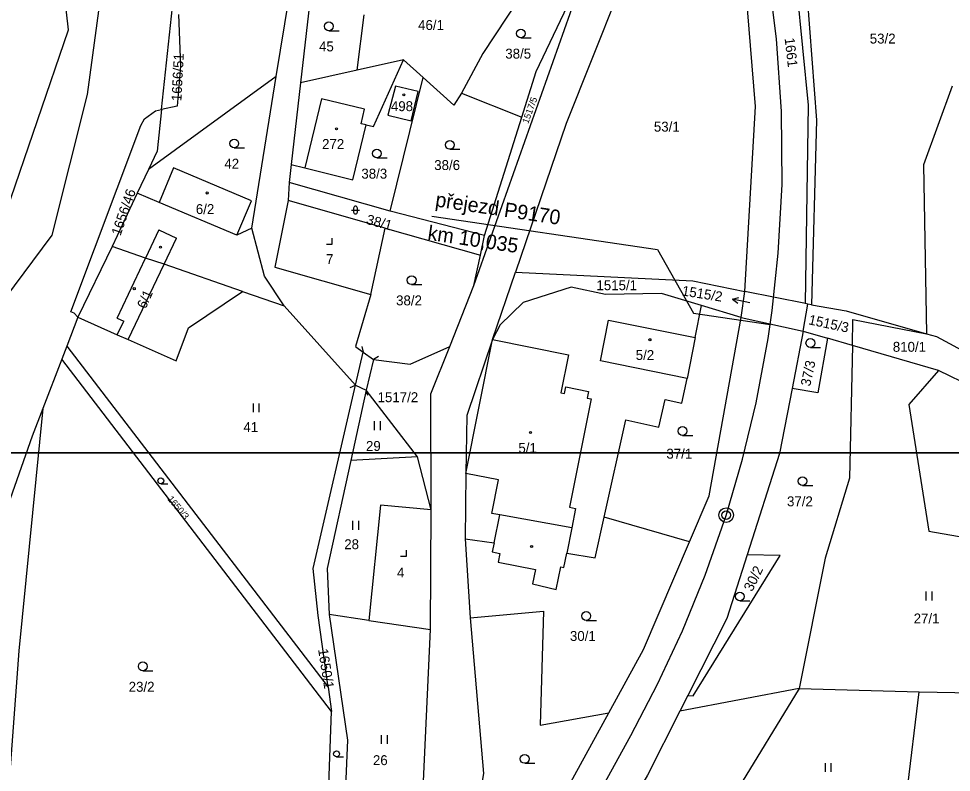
# Model space of a CAD drawing. Extents: x -553916 to -552953, y -1067470 to -1066637.
# Drawn here: x -553633.4 to -553473.7, y -1067154.7 to -1067025.6 of the extents above; entities that cross this region are included whole.
import ezdxf

# ---------------------------------------------------------------- set-up
doc = ezdxf.new("R2010")
doc.units = 0
for name, color, linetype in [('Hranice parcel', 7, 'Continuous'), ('Kolej', 7, 'Continuous'), ('Návěst místo trati', 7, 'Continuous'), ('Parcelní čísla', 7, 'Continuous'), ('Pop  PČ popisy', 7, 'Continuous'), ('Propustek', 7, 'Continuous'), ('Přejezd - štěrkové lože', 7, 'Continuous'), ('Vnitřní kresba', 7, 'Continuous'), ('Vrstva 1', 7, 'Continuous'), ('Značky budov', 7, 'Continuous'), ('Značky kultur', 7, 'Continuous')]:
    doc.layers.add(name, color=color, linetype=linetype)

msp = doc.modelspace()

# ---------------------------------------------------------------- linework, layer by layer
at = {"layer": 'Hranice parcel'}
for p, q in [((-553589.31, -1067035.5), (-553580.85, -1066983.77)), ((-553608.97, -1067041.18), (-553606.12, -1067014.56)), ((-553555.44, -1067071.33), (-553535.85, -1067015.85)), ((-553575.44, -1067034.44), (-553574.24, -1067024.96)), ((-553567.53, -1067032.65), (-553575.44, -1067034.44)), ((-553564.16, -1067035.68), (-553567.53, -1067032.65)), ((-553575.44, -1067034.44), (-553585.14, -1067036.63)), ((-553589.31, -1067035.5), (-553611.2, -1067051.45)), ((-553593.47, -1067061.49), (-553589.31, -1067035.5)), ((-553585.14, -1067036.63), (-553586.75, -1067050.6)), ((-553569.79, -1067058.6), (-553564.16, -1067035.68)), ((-553557.59, -1067038.38), (-553547.23, -1067042.51)), ((-553473.53, -1067037.17), (-553478.45, -1067050.68)), ((-553473.53, -1067037.17), (-553478.45, -1067050.68)), ((-553610, -1067041.4), (-553608.97, -1067041.18)), ((-553606.25, -1067040.6), (-553608.97, -1067041.18)), ((-553553.65, -1067062.79), (-553547.23, -1067042.51)), ((-553586.75, -1067050.6), (-553587.12, -1067053.68)), ((-553586.75, -1067050.6), (-553584.42, -1067051.17)), ((-553478.45, -1067050.68), (-553477.96, -1067079.63)), ((-553478.45, -1067050.68), (-553477.96, -1067079.63)), ((-553611.2, -1067051.45), (-553613.12, -1067055.53)), ((-553587.12, -1067053.68), (-553587.28, -1067056.75)), ((-553569.79, -1067058.6), (-553587.12, -1067053.68)), ((-553613.12, -1067055.53), (-553617.4, -1067064.65)), ((-553609.37, -1067057.11), (-553613.12, -1067055.53)), ((-553570.64, -1067061.48), (-553587.28, -1067056.75)), ((-553553.65, -1067062.79), (-553569.79, -1067058.6)), ((-553593.47, -1067061.49), (-553596.05, -1067062.7)), ((-553573.09, -1067072.86), (-553570.64, -1067061.48)), ((-553570.64, -1067061.48), (-553554.35, -1067066.11)), ((-553554.35, -1067066.11), (-553553.65, -1067062.79)), ((-553617.4, -1067064.65), (-553623.27, -1067076.77)), ((-553555.44, -1067071.33), (-553554.35, -1067066.11)), ((-553552.27, -1067080.57), (-553548.33, -1067069.03)), ((-553559.6, -1067081.76), (-553555.44, -1067071.33)), ((-553595.06, -1067072.35), (-553587.94, -1067074.8)), ((-553575.72, -1067088.37), (-553587.94, -1067074.8)), ((-553517.54, -1067080.21), (-553516.45, -1067074.75)), ((-553509.66, -1067076.78), (-553516.45, -1067074.75)), ((-553623.27, -1067076.77), (-553625.16, -1067081.69)), ((-553490.63, -1067081.59), (-553490.53, -1067077.13)), ((-553490.63, -1067081.59), (-553490.53, -1067077.13)), ((-553490.53, -1067077.13), (-553477.96, -1067079.63)), ((-553490.53, -1067077.13), (-553477.96, -1067079.63)), ((-553517.54, -1067080.21), (-553518.94, -1067087.24)), ((-553490.63, -1067081.59), (-553494.87, -1067080.36)), ((-553475.9, -1067085.87), (-553490.63, -1067081.59)), ((-553625.16, -1067081.69), (-553626.04, -1067083.95)), ((-553625.16, -1067081.69), (-553580.41, -1067140.15)), ((-553575.72, -1067088.37), (-553574.42, -1067082.75)), ((-553574.42, -1067082.75), (-553572.66, -1067084.02)), ((-553626.04, -1067083.95), (-553629.28, -1067092.37)), ((-553579.82, -1067144.32), (-553626.04, -1067083.95)), ((-553572.66, -1067084.02), (-553573.91, -1067089.23)), ((-553461.02, -1067093.19), (-553475.9, -1067085.87)), ((-553573.91, -1067089.23), (-553576.54, -1067101.32)), ((-553565.13, -1067100.69), (-553573.91, -1067089.23)), ((-553565.13, -1067100.69), (-553576.54, -1067101.32)), ((-553562.76, -1067109.76), (-553565.13, -1067100.69)), ((-553562.87, -1067130.27), (-553562.76, -1067109.76)), ((-553518.53, -1067115.26), (-553533.13, -1067110.99)), ((-553556.94, -1067114.69), (-553556.09, -1067128.27)), ((-553573.45, -1067128.7), (-553580.27, -1067127.69)), ((-553573.45, -1067128.7), (-553562.87, -1067130.27)), ((-553580.41, -1067140.15), (-553579.82, -1067144.32)), ((-553499.73, -1067140.34), (-553520.16, -1067144.23)), ((-553499.73, -1067140.34), (-553516.39, -1067167.53)), ((-553499.73, -1067140.34), (-553516.39, -1067167.53)), ((-553499.73, -1067140.34), (-553479.18, -1067140.92)), ((-553482.63, -1067169.28), (-553479.18, -1067140.92)), ((-553479.18, -1067140.92), (-553459.64, -1067141.29)), ((-553581.09, -1067176.52), (-553579.82, -1067144.32))]:
    msp.add_line(p, q, dxfattribs=at)
for points in [[(-553623.32, -1066984.67), (-553619.63, -1066996.83), (-553619.56, -1067023.02), (-553621.7, -1067038.64), (-553627.75, -1067062.69), (-553642.34, -1067082.27), (-553644.52, -1067088.87), (-553655.73, -1067178.24), (-553657.73, -1067185.13), (-553660.17, -1067189.87)], [(-553515.43, -1066991.08), (-553526.38, -1067010.19), (-553539.65, -1067043.59), (-553548.33, -1067069.03)], [(-553547.23, -1067042.51), (-553544.77, -1067034.69), (-553535.85, -1067015.85)], [(-553635.52, -1067058.6), (-553624.9, -1067027.54), (-553625.87, -1067018.94)], [(-553547.68, -1067022.12), (-553553.91, -1067031.58), (-553557.59, -1067038.38)], [(-553582.25, -1067023.44), (-553583.62, -1067023.18), (-553585.14, -1067036.63)], [(-553606.05, -1067024.93), (-553605.71, -1067033.75), (-553606.25, -1067040.6)], [(-553573.91, -1067043.82), (-553572.67, -1067044.12), (-553567.53, -1067032.65)], [(-553557.59, -1067038.38), (-553558.91, -1067040.42), (-553564.16, -1067035.68)], [(-553568.89, -1067037.19), (-553570.19, -1067042.13), (-553566.22, -1067043.1), (-553564.98, -1067038.12), (-553568.89, -1067037.19)], [(-553624.48, -1067075.84), (-553612.48, -1067043.92), (-553611.9, -1067042.79), (-553610, -1067041.4)], [(-553608.97, -1067041.18), (-553609.73, -1067048.33), (-553611.2, -1067051.45)], [(-553584.42, -1067051.17), (-553576.18, -1067053.25), (-553573.91, -1067043.82)], [(-553596.05, -1067062.7), (-553593.57, -1067056.8), (-553606.92, -1067051.2), (-553609.37, -1067057.11)], [(-553587.28, -1067056.75), (-553589.54, -1067068.19), (-553573.09, -1067072.86)], [(-553587.94, -1067074.8), (-553591.32, -1067069.72), (-553593.47, -1067061.49)], [(-553595.06, -1067072.35), (-553608.53, -1067067.7), (-553611.68, -1067066.62), (-553617.4, -1067064.65)], [(-553548.33, -1067069.03), (-553517.95, -1067070.55), (-553509.03, -1067072.35)], [(-553516.45, -1067074.75), (-553523.31, -1067072.7), (-553532.92, -1067072.84), (-553538.78, -1067071.62), (-553547.04, -1067074.23), (-553550.96, -1067078.08), (-553552.27, -1067080.57)], [(-553623.27, -1067076.77), (-553616.54, -1067079.76), (-553614.66, -1067080.6), (-553606.47, -1067084.24), (-553604.34, -1067078.59), (-553595.06, -1067072.35)], [(-553573.09, -1067072.86), (-553575.74, -1067081.8), (-553574.42, -1067082.75)], [(-553497.61, -1067074.62), (-553491.7, -1067075.64), (-553477.96, -1067079.63)], [(-553623.27, -1067076.77), (-553623.9, -1067076.05), (-553624.48, -1067075.84)], [(-553518.94, -1067087.24), (-553533.8, -1067084.25), (-553532.39, -1067077.24), (-553517.54, -1067080.21)], [(-553477.96, -1067079.63), (-553476.25, -1067080.06), (-553464.58, -1067086.32)], [(-553552.27, -1067080.57), (-553556.64, -1067093.58), (-553556.86, -1067103.5), (-553556.94, -1067114.69)], [(-553490.63, -1067081.59), (-553491.15, -1067104.31), (-553495.3, -1067118.01), (-553499.73, -1067140.34)], [(-553490.63, -1067081.59), (-553491.15, -1067104.31), (-553495.3, -1067118.01), (-553499.73, -1067140.34)], [(-553572.66, -1067084.02), (-553566.4, -1067084.81), (-553559.6, -1067081.76)], [(-553562.76, -1067109.76), (-553562.85, -1067089.89), (-553559.6, -1067081.76)], [(-553475.9, -1067085.87), (-553480.97, -1067091.73), (-553477.55, -1067113.39), (-553465.08, -1067115.55)], [(-553533.13, -1067110.99), (-553529.45, -1067094.35), (-553523.77, -1067095.61), (-553522.71, -1067090.83), (-553519.87, -1067091.46), (-553518.94, -1067087.24)], [(-553580.41, -1067140.15), (-553582.14, -1067127.86), (-553583, -1067119.78), (-553575.72, -1067088.37)], [(-553629.28, -1067092.37), (-553631.12, -1067097.14), (-553637.98, -1067116.48)], [(-553629.28, -1067092.37), (-553633.37, -1067133.92), (-553635.66, -1067164.7)], [(-553576.54, -1067101.32), (-553580.57, -1067119.79), (-553580.27, -1067127.69)], [(-553562.76, -1067109.76), (-553571.44, -1067108.95), (-553573.45, -1067128.7)], [(-553540.05, -1067119.63), (-553539.55, -1067117.17), (-553534.67, -1067117.97), (-553533.13, -1067110.99)], [(-553556.94, -1067114.69), (-553551.99, -1067115.38), (-553552.31, -1067116.95)], [(-553552.31, -1067116.95), (-553550.99, -1067117.22), (-553551.28, -1067118.69), (-553544.93, -1067119.96), (-553545.42, -1067122.41), (-553541.36, -1067123.37), (-553540.59, -1067119.53), (-553540.05, -1067119.63)], [(-553518.82, -1067141.56), (-553517.91, -1067141.59), (-553503, -1067117.58), (-553508.67, -1067117.46)], [(-553580.27, -1067127.69), (-553577.12, -1067149.23), (-553578.28, -1067177), (-553579.68, -1067182.05)], [(-553556.09, -1067128.27), (-553543.56, -1067127.12), (-553544.12, -1067146.66), (-553532.35, -1067144.53)], [(-553556.09, -1067128.27), (-553553.82, -1067154.93), (-553557.64, -1067176.88)], [(-553569.54, -1067184.03), (-553564.06, -1067156.23), (-553562.87, -1067130.27)]]:
    msp.add_lwpolyline(points, dxfattribs=at)
at = {"layer": 'Kolej'}
for points in [[(-553503.32, -1067065.81), (-553502.68, -1067054.03), (-553502.76, -1067041.5), (-553503.63, -1067029.06), (-553504.76, -1067019.97), (-553506.18, -1067011.39), (-553508.33, -1067001.39), (-553510.95, -1066991.62), (-553512.92, -1066985.29), (-553515.65, -1066977.35), (-553517.42, -1066972.53), (-553519.16, -1066967.95), (-553522.89, -1066958.38), (-553529.1, -1066942.55), (-553538.69, -1066918.11), (-553542.91, -1066907.33), (-553546.69, -1066897.68), (-553555.03, -1066876.44), (-553564.64, -1066851.89), (-553574.24, -1066827.43), (-553583.19, -1066804.62)], [(-553543.17, -1067173.82), (-553538.26, -1067165.53), (-553533.28, -1067156.93), (-553528.57, -1067148.43), (-553524.02, -1067139.63), (-553519.75, -1067130.49), (-553515.84, -1067120.93), (-553512.27, -1067110.73), (-553509.46, -1067101.06), (-553507.13, -1067091.41), (-553505.08, -1067080.38), (-553504.39, -1067075.58), (-553503.32, -1067065.81)]]:
    msp.add_lwpolyline(points, dxfattribs=at)
at = {"layer": 'Návěst místo trati'}
for radius in [1.25, 0.752]:
    msp.add_circle((-553512.25, -1067110.66), radius, dxfattribs=at)
at = {"layer": 'Pop  PČ popisy'}
for p, q in [((-553511.16, -1067073.68), (-553510.07, -1067073.4)), ((-553508.22, -1067074.31), (-553511.16, -1067073.68)), ((-553511.16, -1067073.68), (-553510.28, -1067074.38))]:
    msp.add_line(p, q, dxfattribs=at)
at = {"layer": 'Propustek'}
for p, q in [((-553499.28, -1067010.65), (-553496.78, -1067043.02)), ((-553496.78, -1067043.02), (-553497.61, -1067074.62)), ((-553498.68, -1067074.42), (-553509.03, -1067072.35)), ((-553498.28, -1067074.5), (-553498.68, -1067074.42)), ((-553497.61, -1067074.62), (-553498.28, -1067074.5))]:
    msp.add_line(p, q, dxfattribs=at)
for points in [[(-553498.68, -1067074.42), (-553498.17, -1067040.43), (-553500.08, -1067020.73), (-553503.77, -1067001.28), (-553507.63, -1066988.97), (-553505.83, -1066988.51)], [(-553509.03, -1067072.35), (-553507.22, -1067040.68), (-553509.18, -1067016.9), (-553515.22, -1066991.69), (-553515.43, -1066991.08)]]:
    msp.add_lwpolyline(points, dxfattribs=at)
at = {"layer": 'Přejezd - štěrkové lože'}
msp.add_lwpolyline([(-553562.67, -1067059.43), (-553524.03, -1067065.17), (-553517.87, -1067076.06), (-553504.74, -1067077.98)], dxfattribs=at)
at = {"layer": 'Vnitřní kresba'}
for p, q in [((-553581.57, -1067039.35), (-553584.42, -1067051.17)), ((-553574.19, -1067041.13), (-553581.57, -1067039.35)), ((-553574.78, -1067043.61), (-553574.19, -1067041.13)), ((-553573.91, -1067043.82), (-553574.78, -1067043.61)), ((-553596.05, -1067062.7), (-553609.37, -1067057.11)), ((-553609.4, -1067061.81), (-553611.68, -1067066.62)), ((-553609.4, -1067061.81), (-553606.41, -1067063.23)), ((-553608.53, -1067067.7), (-553606.41, -1067063.23)), ((-553616.56, -1067076.9), (-553611.68, -1067066.62)), ((-553614.66, -1067080.6), (-553608.53, -1067067.7)), ((-553616.56, -1067076.9), (-553615.43, -1067077.44)), ((-553616.54, -1067079.76), (-553615.43, -1067077.44)), ((-553556.86, -1067103.5), (-553552.27, -1067080.57)), ((-553552.27, -1067080.57), (-553539.23, -1067083.19)), ((-553574.63, -1067081.77), (-553574.42, -1067082.75)), ((-553539.23, -1067083.19), (-553540.54, -1067089.73)), ((-553571.8, -1067083.51), (-553572.66, -1067084.02)), ((-553576.63, -1067088.79), (-553575.72, -1067088.37)), ((-553575.72, -1067088.37), (-553573.91, -1067089.23)), ((-553573.64, -1067090.19), (-553573.91, -1067089.23)), ((-553539.93, -1067089.85), (-553539.7, -1067088.69)), ((-553539.7, -1067088.69), (-553535.83, -1067089.46)), ((-553535.83, -1067089.46), (-553536.06, -1067090.62)), ((-553540.54, -1067089.73), (-553539.93, -1067089.85)), ((-553535.4, -1067090.75), (-553539.11, -1067109.32)), ((-553536.06, -1067090.62), (-553535.4, -1067090.75)), ((-553551.22, -1067104.63), (-553556.86, -1067103.5)), ((-553552.37, -1067110.36), (-553551.22, -1067104.63)), ((-553551.04, -1067110.63), (-553552.37, -1067110.36)), ((-553539.11, -1067109.32), (-553538.03, -1067109.53)), ((-553538.03, -1067109.53), (-553538.68, -1067112.82)), ((-553551.99, -1067115.38), (-553551.04, -1067110.63)), ((-553538.68, -1067112.82), (-553551.04, -1067110.63)), ((-553538.68, -1067112.82), (-553539.55, -1067117.17))]:
    msp.add_line(p, q, dxfattribs=at)
at = {"layer": 'Vrstva 1'}
for p, q in [((-553509.66, -1067076.78), (-553509.03, -1067072.35)), ((-553499.07, -1067079.14), (-553498.28, -1067074.5)), ((-553509.66, -1067076.78), (-553499.07, -1067079.14)), ((-553499.07, -1067079.14), (-553500.97, -1067088.98)), ((-553499.07, -1067079.14), (-553494.87, -1067080.36)), ((-553518.82, -1067141.56), (-553520.16, -1067144.23))]:
    msp.add_line(p, q, dxfattribs=at)
for points in [[(-553300, -1066816.27), (-553300, -1067100), (-553800, -1067100), (-553800, -1066816.27)], [(-553518.53, -1067115.26), (-553515.16, -1067107.38), (-553509.66, -1067076.78)], [(-553494.87, -1067080.36), (-553496.55, -1067089.69), (-553500.97, -1067088.98)], [(-553500.97, -1067088.98), (-553503.12, -1067100.12), (-553508.67, -1067117.46)], [(-553800, -1067410.27), (-553800, -1067100), (-553300, -1067100), (-553300, -1067410.27)], [(-553532.35, -1067144.53), (-553526.4, -1067133.68), (-553518.53, -1067115.26)], [(-553508.67, -1067117.46), (-553512.16, -1067128.37), (-553518.82, -1067141.56)], [(-553551.38, -1067177.98), (-553539.14, -1067156.92), (-553532.35, -1067144.53)], [(-553520.16, -1067144.23), (-553525.7, -1067155.19), (-553540.6, -1067180.86)]]:
    msp.add_lwpolyline(points, dxfattribs=at)
at = {"layer": 'Značky budov'}
for centre in [(-553567.44, -1067038.66), (-553579, -1067044.5), (-553601.13, -1067055.48), (-553609.12, -1067064.77), (-553613.62, -1067071.87), (-553525.3, -1067080.61), (-553545.78, -1067096.51), (-553545.57, -1067116.03)]:
    msp.add_circle(centre, 0.175, dxfattribs=at)
at = {"layer": 'Značky kultur'}
for p, q in [((-553580.29, -1067027.68), (-553578.54, -1067027.68)), ((-553547.42, -1067028.91), (-553545.67, -1067028.91)), ((-553596.5, -1067047.76), (-553594.75, -1067047.76)), ((-553559.59, -1067048), (-553557.84, -1067048)), ((-553572.07, -1067049.47), (-553570.32, -1067049.47)), ((-553576.4, -1067058.4), (-553575.06, -1067058.4)), ((-553576.07, -1067058.06), (-553576.07, -1067058.74)), ((-553575.4, -1067058.74), (-553575.4, -1067058.06)), ((-553579.73, -1067064.23), (-553579.73, -1067063.23)), ((-553580.73, -1067064.23), (-553579.73, -1067064.23)), ((-553566.12, -1067071.18), (-553564.37, -1067071.18)), ((-553497.83, -1067081.93), (-553496.08, -1067081.93)), ((-553593.23, -1067093.03), (-553593.23, -1067091.53)), ((-553592.23, -1067093.03), (-553592.23, -1067091.53)), ((-553572.46, -1067096.09), (-553572.46, -1067094.59)), ((-553571.46, -1067096.09), (-553571.46, -1067094.59)), ((-553519.72, -1067097), (-553517.97, -1067097)), ((-553609.07, -1067105.28), (-553607.9, -1067105.28)), ((-553499.17, -1067105.6), (-553497.42, -1067105.6)), ((-553576.19, -1067113.16), (-553576.19, -1067111.66)), ((-553575.19, -1067113.16), (-553575.19, -1067111.66)), ((-553567.02, -1067117.68), (-553567.02, -1067116.68)), ((-553568.02, -1067117.68), (-553567.02, -1067117.68)), ((-553477.99, -1067125.26), (-553477.99, -1067123.76)), ((-553476.99, -1067125.26), (-553476.99, -1067123.76)), ((-553509.92, -1067125.35), (-553508.17, -1067125.35)), ((-553536.21, -1067128.68), (-553534.46, -1067128.68)), ((-553612.17, -1067137.31), (-553610.42, -1067137.31)), ((-553571.26, -1067149.83), (-553571.26, -1067148.33)), ((-553570.26, -1067149.83), (-553570.26, -1067148.33)), ((-553578.97, -1067152.05), (-553577.8, -1067152.05)), ((-553546.76, -1067153.17), (-553545.01, -1067153.17)), ((-553495.26, -1067154.62), (-553495.26, -1067153.12)), ((-553494.26, -1067154.62), (-553494.26, -1067153.12))]:
    msp.add_line(p, q, dxfattribs=at)
for centre, radius in [((-553580.29, -1067026.93), 0.75), ((-553547.42, -1067028.16), 0.75), ((-553596.5, -1067047.01), 0.75), ((-553572.07, -1067048.72), 0.75), ((-553559.59, -1067047.25), 0.75), ((-553566.12, -1067070.43), 0.75), ((-553497.83, -1067081.18), 0.75), ((-553519.72, -1067096.25), 0.75), ((-553609.08, -1067104.78), 0.502), ((-553499.17, -1067104.85), 0.75), ((-553509.92, -1067124.6), 0.75), ((-553536.21, -1067127.93), 0.75), ((-553612.17, -1067136.56), 0.75), ((-553578.98, -1067151.55), 0.502), ((-553546.76, -1067152.42), 0.75)]:
    msp.add_circle(centre, radius, dxfattribs=at)
for centre, start, end in [((-553575.73, -1067058.07), 0, 180), ((-553575.73, -1067058.74), 180, 359.9879)]:
    msp.add_arc(centre, 0.335, start, end, dxfattribs=at)

# ---------------------------------------------------------------- texts
at = {"layer": 'Parcelní čísla'}
for s, p in [('46/1', (-553565.01, -1067027.56)), ('53/2', (-553487.66, -1067029.88)), ('45', (-553581.98, -1067031.23)), ('38/5', (-553550.08, -1067032.46)), ('498', (-553569.67, -1067041.46)), ('53/1', (-553524.63, -1067044.97)), ('272', (-553581.46, -1067047.94)), ('42', (-553598.19, -1067051.31)), ('38/3', (-553574.73, -1067053.02)), ('38/6', (-553562.25, -1067051.55)), ('6/2', (-553603.08, -1067059.09)), ('7', (-553580.77, -1067067.65)), ('1515/1', (-553534.47, -1067072.13)), ('38/2', (-553568.78, -1067074.73)), ('810/1', (-553483.71, -1067082.68)), ('5/2', (-553527.74, -1067084.08)), ('1517/2', (-553571.95, -1067091.31)), ('41', (-553594.93, -1067096.42)), ('29', (-553573.94, -1067099.66)), ('5/1', (-553547.84, -1067100)), ('37/1', (-553522.49, -1067100.99)), ('37/2', (-553501.83, -1067109.15)), ('28', (-553577.66, -1067116.49)), ('4', (-553568.62, -1067121.33)), ('27/1', (-553480.14, -1067129.21)), ('30/1', (-553539.01, -1067132.21)), ('23/2', (-553614.58, -1067140.91)), ('26', (-553572.75, -1067153.48))]:
    msp.add_text(s, height=1.7, dxfattribs=at).set_placement(p)
for s, height, rotation, p in [('1656/51', 1.7, 87, (-553605.56, -1067039.79)), ('1517/5', 1.14, 70, (-553546.16, -1067043.69)), ('1656/46', 1.7, 71, (-553615.99, -1067062.91)), ('38/1', 1.7, 345, (-553574, -1067060.76)), ('6/1', 1.7, 66, (-553611.68, -1067075.45)), ('1515/3', 1.7, 348, (-553498.25, -1067077.96)), ('1650/3', 1.14, 310, (-553608.01, -1067107.95)), ('30/2', 1.7, 64, (-553507.8, -1067123.87)), ('1650/1', 1.7, 279, (-553582.15, -1067133.66))]:
    msp.add_text(s, height=height, rotation=rotation, dxfattribs=at).set_placement(p)
at = {"layer": 'Přejezd - štěrkové lože'}
for s, p in [('přejezd P9170', (-553562.17, -1067057.78)), ('km 10,035', (-553563.49, -1067063.48))]:
    msp.add_text(s, height=2.5, rotation=351.5622, dxfattribs=at).set_placement(p)
at = {"layer": 'Vrstva 1'}
for s, rotation, p in [('1661', 276.6165, (-553502.25, -1067028.98)), ('1515/2', 351, (-553519.91, -1067073.02)), ('37/3', 78, (-553497.86, -1067088.69))]:
    msp.add_text(s, height=1.7, rotation=rotation, dxfattribs=at).set_placement(p)

doc.saveas('drawing.dxf')
